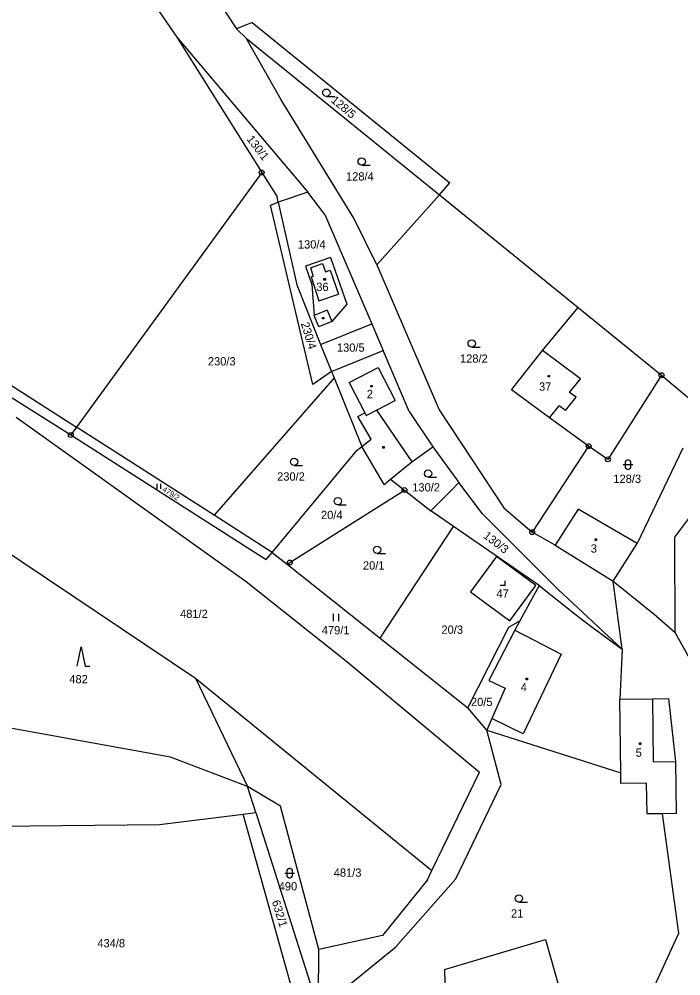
# Model space of a CAD drawing. Extents: x -794421 to -792735, y -1117671 to -1115559.
# Drawn here: x -793541.7 to -793405.9, y -1116892.5 to -1116696.2 of the extents above; entities that cross this region are included whole.
import ezdxf

# ---------------------------------------------------------------- set-up
doc = ezdxf.new("R2010")
doc.units = 0
for name, color, linetype in [('Vrstva 1', 7, 'Continuous'), ('Vrstva 14', 7, 'Continuous'), ('Vrstva 15', 7, 'Continuous'), ('Vrstva 2', 7, 'Continuous'), ('Vrstva 23', 7, 'Continuous'), ('Vrstva 25', 7, 'Continuous'), ('Vrstva 28', 7, 'Continuous')]:
    doc.layers.add(name, color=color, linetype=linetype)

msp = doc.modelspace()

# ---------------------------------------------------------------- linework, layer by layer
at = {"layer": 'Vrstva 1'}
for p, q in [((-793516.41, -1116669.13), (-793497.1, -1116698.22)), ((-793528.9, -1116671.42), (-793509.4, -1116699.91)), ((-793493.88, -1116696.89), (-793497.1, -1116698.22)), ((-793497.1, -1116698.22), (-793495.13, -1116700.1)), ((-793493.88, -1116696.89), (-793453.32, -1116729.83)), ((-793509.4, -1116699.91), (-793482.51, -1116731.76)), ((-793509.4, -1116699.91), (-793491.96, -1116727.69)), ((-793495.13, -1116700.1), (-793455.5, -1116732.28)), ((-793487.96, -1116712.78), (-793495.13, -1116700.1)), ((-793473.06, -1116737.06), (-793487.96, -1116712.78)), ((-793491.96, -1116727.69), (-793529.97, -1116779.96)), ((-793491.96, -1116727.69), (-793488.81, -1116732.71)), ((-793455.5, -1116732.28), (-793453.32, -1116729.83)), ((-793482.51, -1116731.76), (-793488.57, -1116733.79)), ((-793479.02, -1116736.3), (-793482.51, -1116731.76)), ((-793490.16, -1116734.37), (-793488.57, -1116733.79)), ((-793488.57, -1116733.79), (-793488.81, -1116732.71)), ((-793488.57, -1116733.79), (-793484.77, -1116750.75)), ((-793468.31, -1116746.66), (-793455.5, -1116732.28)), ((-793455.5, -1116732.28), (-793427.03, -1116755.39)), ((-793481.48, -1116771.21), (-793490.16, -1116734.37)), ((-793479.02, -1116736.3), (-793469.39, -1116758.76)), ((-793468.31, -1116746.66), (-793473.06, -1116737.06)), ((-793477.87, -1116745.12), (-793482.97, -1116746.91)), ((-793477.87, -1116745.12), (-793474.52, -1116754.73)), ((-793482.97, -1116746.91), (-793481.69, -1116750.7)), ((-793468.31, -1116746.66), (-793455.51, -1116776.4)), ((-793484.77, -1116750.75), (-793479.86, -1116762.98)), ((-793481.69, -1116750.7), (-793481.19, -1116757.04)), ((-793474.52, -1116754.73), (-793477.58, -1116758.28)), ((-793434.36, -1116764.23), (-793427.03, -1116755.39)), ((-793427.03, -1116755.39), (-793409.92, -1116769.28)), ((-793480.25, -1116759.36), (-793481.19, -1116757.04)), ((-793477.58, -1116758.28), (-793480.25, -1116759.36)), ((-793479.86, -1116762.98), (-793469.39, -1116758.76)), ((-793469.39, -1116758.76), (-793467.04, -1116764.23)), ((-793560.85, -1116760.22), (-793529.97, -1116779.96)), ((-793479.86, -1116762.98), (-793477.64, -1116768.5)), ((-793477.64, -1116768.5), (-793467.04, -1116764.23)), ((-793461.69, -1116776.71), (-793467.04, -1116764.23)), ((-793440.72, -1116772.31), (-793434.36, -1116764.23)), ((-793477.64, -1116768.5), (-793481.48, -1116771.21)), ((-793477.64, -1116768.5), (-793477.11, -1116769.82)), ((-793409.92, -1116769.28), (-793420.92, -1116786.56)), ((-793409.92, -1116769.28), (-793399.55, -1116777.99)), ((-793477.11, -1116769.82), (-793501.74, -1116798.01)), ((-793477.11, -1116769.82), (-793471.4, -1116783.91)), ((-793432.87, -1116778.03), (-793440.72, -1116772.31)), ((-793543.13, -1116773.91), (-793531.13, -1116781.55)), ((-793461.69, -1116776.71), (-793456.86, -1116783.98)), ((-793455.51, -1116776.4), (-793442.28, -1116796.53)), ((-793542.35, -1116777.91), (-793495.16, -1116811.62)), ((-793424.87, -1116783.86), (-793432.87, -1116778.03)), ((-793529.97, -1116779.96), (-793531.13, -1116781.55)), ((-793501.74, -1116798.01), (-793529.97, -1116779.96)), ((-793531.13, -1116781.55), (-793491.01, -1116807.11)), ((-793489.78, -1116805.66), (-793472.43, -1116784.72)), ((-793472.43, -1116784.72), (-793471.4, -1116783.91)), ((-793466.85, -1116791.69), (-793471.4, -1116783.91)), ((-793461.14, -1116787.05), (-793456.86, -1116783.98)), ((-793456.86, -1116783.98), (-793451.5, -1116791.32)), ((-793424.87, -1116783.86), (-793436.46, -1116801.5)), ((-793420.92, -1116786.56), (-793424.87, -1116783.86)), ((-793405.56, -1116784.23), (-793414.95, -1116803.81)), ((-793407.19, -1116802.49), (-793394.89, -1116786.04)), ((-793465.51, -1116790.6), (-793461.14, -1116787.05)), ((-793466.85, -1116791.69), (-793465.51, -1116790.6)), ((-793465.51, -1116790.6), (-793462.65, -1116792.86)), ((-793453.11, -1116792.93), (-793451.5, -1116791.32)), ((-793446.66, -1116797.75), (-793451.5, -1116791.32)), ((-793486.19, -1116807.71), (-793462.65, -1116792.86)), ((-793462.65, -1116792.86), (-793457.28, -1116797.09)), ((-793457.28, -1116797.09), (-793453.11, -1116792.93)), ((-793442.28, -1116796.53), (-793436.46, -1116801.5)), ((-793427.03, -1116796.76), (-793431.74, -1116804.17)), ((-793414.95, -1116803.81), (-793427.03, -1116796.76)), ((-793489.78, -1116805.66), (-793501.74, -1116798.01)), ((-793452.63, -1116800.3), (-793457.28, -1116797.09)), ((-793431.03, -1116813.35), (-793446.66, -1116797.75)), ((-793467.65, -1116823.23), (-793452.63, -1116800.3)), ((-793435.03, -1116812.45), (-793452.63, -1116800.3)), ((-793550.33, -1116801.48), (-793505.53, -1116831.44)), ((-793431.74, -1116804.17), (-793436.46, -1116801.5)), ((-793407.1, -1116822.08), (-793407.19, -1116802.49)), ((-793431.74, -1116804.17), (-793419.81, -1116811.57)), ((-793419.81, -1116811.57), (-793414.95, -1116803.81)), ((-793491.01, -1116807.11), (-793489.78, -1116805.66)), ((-793489.78, -1116805.66), (-793486.75, -1116808.07)), ((-793443.75, -1116806.47), (-793449.14, -1116813.75)), ((-793435.74, -1116812.41), (-793443.75, -1116806.47)), ((-793486.75, -1116808.07), (-793486.19, -1116807.71)), ((-793486.75, -1116808.07), (-793467.65, -1116823.23)), ((-793495.16, -1116811.62), (-793474.5, -1116828.06)), ((-793441.07, -1116819.72), (-793435.74, -1116812.41)), ((-793435.03, -1116812.45), (-793438.97, -1116819.69)), ((-793435.03, -1116812.45), (-793427.62, -1116818.29)), ((-793418.01, -1116825.47), (-793419.81, -1116811.57)), ((-793419.81, -1116811.57), (-793411.42, -1116818.31)), ((-793449.14, -1116813.75), (-793441.07, -1116819.72)), ((-793418.01, -1116825.47), (-793431.03, -1116813.35)), ((-793427.62, -1116818.29), (-793425.6, -1116819.88)), ((-793411.42, -1116818.31), (-793407.1, -1116822.08)), ((-793441.28, -1116820.97), (-793438.97, -1116819.69)), ((-793438.97, -1116819.69), (-793440.03, -1116821.63)), ((-793425.6, -1116819.88), (-793424.43, -1116820.81)), ((-793449.66, -1116837.51), (-793441.28, -1116820.97)), ((-793440.03, -1116821.63), (-793445.34, -1116831.95)), ((-793424.43, -1116820.81), (-793418.01, -1116825.47)), ((-793393.6, -1116846.5), (-793407.1, -1116822.08)), ((-793467.65, -1116823.23), (-793449.66, -1116837.51)), ((-793418.01, -1116825.47), (-793418.47, -1116835.78)), ((-793474.5, -1116828.06), (-793447.3, -1116850.74)), ((-793505.53, -1116831.44), (-793457.06, -1116870.95)), ((-793505.53, -1116831.44), (-793494.9, -1116853.71)), ((-793445.34, -1116831.95), (-793442.03, -1116833.5)), ((-793442.03, -1116833.5), (-793444.71, -1116839.7)), ((-793418.47, -1116835.78), (-793411.79, -1116835.69)), ((-793418.3, -1116850.88), (-793418.47, -1116835.78)), ((-793411.79, -1116835.69), (-793408.47, -1116835.65)), ((-793408.47, -1116835.65), (-793407.03, -1116848.53)), ((-793445.75, -1116842.1), (-793449.66, -1116837.51)), ((-793444.71, -1116839.7), (-793445.75, -1116842.1)), ((-793510.66, -1116847.67), (-793547.25, -1116841.03)), ((-793445.75, -1116842.1), (-793418.3, -1116850.88)), ((-793442.82, -1116853.29), (-793445.75, -1116842.1)), ((-793494.9, -1116853.71), (-793510.66, -1116847.67)), ((-793407.03, -1116848.53), (-793406.89, -1116859.23)), ((-793457.06, -1116870.95), (-793447.3, -1116850.74)), ((-793418.27, -1116853.08), (-793418.3, -1116850.88)), ((-793452.09, -1116872.6), (-793442.82, -1116853.29)), ((-793412.97, -1116853.01), (-793418.27, -1116853.08)), ((-793412.89, -1116859.31), (-793412.97, -1116853.01)), ((-793493.13, -1116859), (-793494.9, -1116853.71)), ((-793488.12, -1116857.75), (-793494.9, -1116853.71)), ((-793512.95, -1116861.51), (-793495.76, -1116859.33)), ((-793495.76, -1116859.33), (-793493.13, -1116859)), ((-793484.35, -1116900.11), (-793495.76, -1116859.33)), ((-793493.13, -1116859), (-793480.31, -1116899.44)), ((-793480.23, -1116887.15), (-793488.12, -1116857.75)), ((-793409.69, -1116859.27), (-793412.89, -1116859.31)), ((-793406.89, -1116859.23), (-793409.69, -1116859.27)), ((-793406.34, -1116883.78), (-793409.69, -1116859.27)), ((-793550.52, -1116861.88), (-793512.95, -1116861.51)), ((-793457.95, -1116872.82), (-793457.06, -1116870.95)), ((-793457.95, -1116872.82), (-793467.14, -1116884.26)), ((-793464.48, -1116886.66), (-793452.09, -1116872.6)), ((-793467.14, -1116884.26), (-793480.23, -1116887.15)), ((-793454.44, -1116891.23), (-793433.75, -1116885.1)), ((-793433.75, -1116885.1), (-793430.93, -1116895.01)), ((-793412.98, -1116898.15), (-793406.34, -1116883.78)), ((-793480.31, -1116899.44), (-793464.48, -1116886.66)), ((-793480.31, -1116899.44), (-793480.23, -1116887.15)), ((-793454.44, -1116891.23), (-793454, -1116913.82))]:
    msp.add_line(p, q, dxfattribs=at)
at = {"layer": 'Vrstva 2'}
for p, q in [((-793481.95, -1116747.24), (-793479.45, -1116746.36)), ((-793481.95, -1116747.24), (-793481.41, -1116748.96)), ((-793479.45, -1116746.36), (-793478.86, -1116748.06)), ((-793481.79, -1116749.09), (-793481.41, -1116748.96)), ((-793481.79, -1116749.09), (-793480.22, -1116754.06)), ((-793478.86, -1116748.06), (-793477.92, -1116747.73)), ((-793477.92, -1116747.73), (-793476.2, -1116752.65)), ((-793480.22, -1116754.06), (-793476.2, -1116752.65)), ((-793478.52, -1116755.96), (-793481.19, -1116757.04)), ((-793478.52, -1116755.96), (-793477.58, -1116758.28)), ((-793426.56, -1116770.01), (-793434.36, -1116764.23)), ((-793474.01, -1116770.8), (-793468.03, -1116767.7)), ((-793468.03, -1116767.7), (-793464.54, -1116774.45)), ((-793474.01, -1116770.8), (-793470.79, -1116777.02)), ((-793428.79, -1116772.84), (-793426.56, -1116770.01)), ((-793427.46, -1116773.81), (-793428.79, -1116772.84)), ((-793468.39, -1116776.44), (-793464.54, -1116774.45)), ((-793429.59, -1116776.52), (-793427.46, -1116773.81)), ((-793472.21, -1116777.75), (-793470.79, -1116777.02)), ((-793470.79, -1116777.02), (-793470.52, -1116777.55)), ((-793470.52, -1116777.55), (-793468.39, -1116776.44)), ((-793468.39, -1116776.44), (-793461.14, -1116787.05)), ((-793432.87, -1116778.03), (-793430.92, -1116775.55)), ((-793429.59, -1116776.52), (-793430.92, -1116775.55)), ((-793469.51, -1116782.43), (-793472.21, -1116777.75)), ((-793471.4, -1116783.91), (-793469.51, -1116782.43)), ((-793440.03, -1116821.63), (-793430.52, -1116826.51)), ((-793430.52, -1116826.51), (-793438.28, -1116842.88)), ((-793411.79, -1116835.69), (-793411.63, -1116848.59)), ((-793438.28, -1116842.88), (-793444.71, -1116839.7)), ((-793411.63, -1116848.59), (-793407.03, -1116848.53))]:
    msp.add_line(p, q, dxfattribs=at)
at = {"layer": 'Vrstva 23'}
for p, q in [((-793478.69, -1116712.07), (-793476.94, -1116712.07)), ((-793471.44, -1116726.19), (-793469.69, -1116726.19)), ((-793448.87, -1116763.52), (-793447.12, -1116763.52)), ((-793417.3, -1116787.04), (-793417.2, -1116786.84)), ((-793417.2, -1116786.84), (-793417.1, -1116786.74)), ((-793417.1, -1116786.74), (-793416.9, -1116786.64)), ((-793416.9, -1116786.64), (-793416.7, -1116786.64)), ((-793416.7, -1116786.64), (-793416.5, -1116786.74)), ((-793416.5, -1116786.74), (-793416.4, -1116786.84)), ((-793416.4, -1116786.84), (-793416.3, -1116787.04)), ((-793485.32, -1116787.81), (-793483.57, -1116787.81)), ((-793417.8, -1116787.64), (-793415.8, -1116787.64)), ((-793417.3, -1116788.24), (-793417.3, -1116787.04)), ((-793417.2, -1116788.44), (-793417.3, -1116788.24)), ((-793417.1, -1116788.54), (-793417.2, -1116788.44)), ((-793416.9, -1116788.64), (-793417.1, -1116788.54)), ((-793416.7, -1116788.64), (-793416.9, -1116788.64)), ((-793416.5, -1116788.54), (-793416.7, -1116788.64)), ((-793416.4, -1116788.44), (-793416.5, -1116788.54)), ((-793416.3, -1116788.24), (-793416.4, -1116788.44)), ((-793416.3, -1116787.04), (-793416.3, -1116788.24)), ((-793457.82, -1116790.23), (-793456.07, -1116790.23)), ((-793513.405, -1116792.58), (-793513.405, -1116791.575)), ((-793512.735, -1116791.575), (-793512.735, -1116792.58)), ((-793476.35, -1116795.9), (-793474.6, -1116795.9)), ((-793468.29, -1116805.86), (-793466.54, -1116805.86)), ((-793442.02, -1116812.45), (-793443.02, -1116812.45)), ((-793442.02, -1116812.45), (-793442.02, -1116811.45)), ((-793477.19, -1116819.75), (-793477.19, -1116818.25)), ((-793476.19, -1116818.25), (-793476.19, -1116819.75)), ((-793529.79, -1116829.01), (-793528.99, -1116825.01)), ((-793528.99, -1116825.01), (-793528.19, -1116829.01)), ((-793528.19, -1116829.01), (-793527.19, -1116829.01)), ((-793486.73, -1116870.87), (-793486.63, -1116870.67)), ((-793486.73, -1116872.07), (-793486.73, -1116870.87)), ((-793486.63, -1116870.67), (-793486.53, -1116870.57)), ((-793486.53, -1116870.57), (-793486.33, -1116870.47)), ((-793486.33, -1116870.47), (-793486.13, -1116870.47)), ((-793486.13, -1116870.47), (-793485.93, -1116870.57)), ((-793485.93, -1116870.57), (-793485.83, -1116870.67)), ((-793485.83, -1116870.67), (-793485.73, -1116870.87)), ((-793485.73, -1116870.87), (-793485.73, -1116872.07)), ((-793487.23, -1116871.47), (-793485.23, -1116871.47)), ((-793486.63, -1116872.27), (-793486.73, -1116872.07)), ((-793486.53, -1116872.37), (-793486.63, -1116872.27)), ((-793486.33, -1116872.47), (-793486.53, -1116872.37)), ((-793486.13, -1116872.47), (-793486.33, -1116872.47)), ((-793485.93, -1116872.37), (-793486.13, -1116872.47)), ((-793485.83, -1116872.27), (-793485.93, -1116872.37)), ((-793485.73, -1116872.07), (-793485.83, -1116872.27)), ((-793439.17, -1116877.43), (-793437.42, -1116877.43))]:
    msp.add_line(p, q, dxfattribs=at)
for centre in [(-793478.69, -1116711.32), (-793471.44, -1116725.44), (-793448.87, -1116762.77), (-793485.32, -1116787.06), (-793457.82, -1116789.48), (-793476.35, -1116795.15), (-793468.29, -1116805.11), (-793439.17, -1116876.68)]:
    msp.add_circle(centre, 0.75, dxfattribs=at)
at = {"layer": 'Vrstva 25'}
for p, q in [((-793479.19, -1116749.47), (-793478.89, -1116749.47)), ((-793479.19, -1116749.77), (-793479.19, -1116749.47)), ((-793478.89, -1116749.47), (-793478.89, -1116749.77)), ((-793478.89, -1116749.77), (-793479.19, -1116749.77)), ((-793479.51, -1116757.43), (-793479.21, -1116757.43)), ((-793479.51, -1116757.73), (-793479.51, -1116757.43)), ((-793479.21, -1116757.43), (-793479.21, -1116757.73)), ((-793479.21, -1116757.73), (-793479.51, -1116757.73)), ((-793433.21, -1116769.33), (-793432.91, -1116769.33)), ((-793433.21, -1116769.63), (-793433.21, -1116769.33)), ((-793432.91, -1116769.63), (-793433.21, -1116769.63)), ((-793432.91, -1116769.33), (-793432.91, -1116769.63)), ((-793469.57, -1116771.4), (-793469.27, -1116771.4)), ((-793469.57, -1116771.7), (-793469.57, -1116771.4)), ((-793469.27, -1116771.7), (-793469.57, -1116771.7)), ((-793469.27, -1116771.4), (-793469.27, -1116771.7)), ((-793467.13, -1116783.95), (-793466.83, -1116783.95)), ((-793467.13, -1116784.25), (-793467.13, -1116783.95)), ((-793466.83, -1116784.25), (-793467.13, -1116784.25)), ((-793466.83, -1116783.95), (-793466.83, -1116784.25)), ((-793423.54, -1116802.89), (-793423.24, -1116802.89)), ((-793423.54, -1116803.19), (-793423.54, -1116802.89)), ((-793423.24, -1116803.19), (-793423.54, -1116803.19)), ((-793423.24, -1116802.89), (-793423.24, -1116803.19)), ((-793437.7, -1116831.48), (-793437.4, -1116831.48)), ((-793437.7, -1116831.78), (-793437.7, -1116831.48)), ((-793437.4, -1116831.78), (-793437.7, -1116831.78)), ((-793437.4, -1116831.48), (-793437.4, -1116831.78)), ((-793414.43, -1116844.75), (-793414.13, -1116844.75)), ((-793414.43, -1116845.05), (-793414.43, -1116844.75)), ((-793414.13, -1116845.05), (-793414.43, -1116845.05)), ((-793414.13, -1116844.75), (-793414.13, -1116845.05))]:
    msp.add_line(p, q, dxfattribs=at)
at = {"layer": 'Vrstva 28'}
for centre, radius in [((-793491.96, -1116727.69), 0.5), ((-793491.96, -1116727.69), 0.01), ((-793409.92, -1116769.28), 0.5), ((-793409.92, -1116769.28), 0.01), ((-793531.13, -1116781.55), 0.5), ((-793531.13, -1116781.55), 0.01), ((-793424.87, -1116783.86), 0.5), ((-793424.87, -1116783.86), 0.01), ((-793420.92, -1116786.56), 0.5), ((-793420.92, -1116786.56), 0.01), ((-793462.65, -1116792.86), 0.5), ((-793462.65, -1116792.86), 0.01), ((-793436.46, -1116801.5), 0.5), ((-793436.46, -1116801.5), 0.01), ((-793486.19, -1116807.71), 0.5), ((-793486.19, -1116807.71), 0.01)]:
    msp.add_circle(centre, radius, dxfattribs=at)

# ---------------------------------------------------------------- texts
at = {"layer": 'Vrstva 14'}
for s, height, rotation, p in [('128/5', 1.7, 320.27022, (-793477.876, -1116713.106)), ('130/1', 1.7, 307.54215, (-793495.133, -1116720.88)), ('230/4', 1.7, 286.97868, (-793483.934, -1116758.686)), ('479/2', 1.14, 327.49749, (-793512.472, -1116793)), ('130/3', 1.7, 322.26453, (-793446.628, -1116802.516)), ('632/1', 1.7, 287.09694, (-793489.899, -1116877.28))]:
    msp.add_text(s, height=height, rotation=rotation, dxfattribs=at).set_placement(p)
for s, p in [('128/4', (-793474.659, -1116729.34)), ('130/4', (-793484.528, -1116743.3)), ('130/5', (-793476.519, -1116764.47)), ('128/2', (-793451.263, -1116766.72)), ('230/3', (-793502.999, -1116767.28)), ('230/2', (-793488.799, -1116790.92)), ('128/3', (-793419.803, -1116791.39)), ('130/2', (-793461.072, -1116793.15)), ('20/4', (-793479.785, -1116798.81)), ('20/1', (-793471.182, -1116809.17)), ('481/2', (-793508.709, -1116819.1)), ('479/1', (-793479.626, -1116822.46)), ('20/3', (-793455.069, -1116822.35)), ('482', (-793531.432, -1116832.52)), ('20/5', (-793449.015, -1116837.18)), ('481/3', (-793477.179, -1116872.2)), ('490', (-793488.462, -1116875.01)), ('21', (-793440.81, -1116880.58)), ('434/8', (-793525.681, -1116886.69))]:
    msp.add_text(s, height=1.7, dxfattribs=at).set_placement(p)
at = {"layer": 'Vrstva 15'}
for s, p in [('36', (-793480.757, -1116752.01)), ('37', (-793435.053, -1116772.47)), ('2', (-793470.387, -1116774)), ('3', (-793424.437, -1116805.7)), ('47', (-793443.789, -1116814.92)), ('4', (-793438.813, -1116834.16)), ('5', (-793415.223, -1116847.58))]:
    msp.add_text(s, height=1.7, dxfattribs=at).set_placement(p)

doc.saveas('drawing.dxf')
